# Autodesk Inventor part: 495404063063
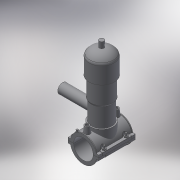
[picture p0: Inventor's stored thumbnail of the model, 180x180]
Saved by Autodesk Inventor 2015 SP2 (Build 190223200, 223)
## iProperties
Created: 2017-07
Part Number: 495404063063
Material: Generic
Description: PLASSON TAPPING VALVE 63-63
Document SubType Name: Modeling
Designer: KIM
Density: 1 g/cm^3
Appearance: Default
Author: KIM
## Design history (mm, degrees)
derived "495404-4954S4.ipt"
feature "Solid1::495404-4954S4.ipt"
feature "Solid2::495404-4954S4.ipt"
tag "TaggingFeature1"
body "Solid1"
body "Solid2"
other parameters: "d_" = 63, "B_" = 99, "H_" = 186, "L_" = 118, "d_t" = 6, "d_1" = 63, "H_1" = 51, "H_2" = 244, "d148" = 0.945, "d160" = 0.945, "d169" = 3, "d192" = 6.8, "d228" = 50.4, "d0" = 63, "d2" = 99, "d3" = 15.75, "d4" = 118, "d5" = 0, "d6" = 0.1, "d8" = 0, "d19" = 6, "d20" = 6, "d21" = 70.8, "d23" = 0, "d24" = 35.4, "d26" = 0, "d27" = 3, "d28" = 3, "d29" = 3, "d30" = 21, "d31" = 6, "d32" = 0, "d33" = 0, "d34" = 0.6, "d40" = 42.588, "d47" = 91.95, "d70" = 15, "d72" = 0, "d73" = 6, "d75" = 5, "d76" = 0, "d77" = 3.15, "d78" = 61.5, "d79" = 15, "d80" = 47.2, "d82" = 5 deg, "d84" = 4, "d85" = 14, "d86" = 0, "d87" = 3, "d88" = 0, "d89" = 1, "d90" = 1, "d91" = 94.4, "d92" = 0, "d93" = 0.5, "d94" = 33.15789, "d96" = 84.357, "d97" = 2.36, "d98" = 0, "d120" = 140 deg, "d121" = 24.228, "d122" = 20 deg, "d123" = 163.8, "d124" = 49.14, "d126" = 0, "d143" = 64.89, "d145" = 14.53846, "d149" = 0.945, "d150" = 15.99231, "d153" = 118, "d154" = 0, "d156" = 40.95, "d157" = 160 deg, "d159" = 3.78, "d161" = 0.945, "d162" = 70.8, "d163" = 0, "d164" = 31.5, "d167" = 6.3, "d168" = 39.95122, "d170" = 3, "d172" = 0, "d173" = 1, "d175" = 31.5, "d176" = 20 deg, "d177" = 4.41, "d178" = 18.9, "d180" = 0, "d183" = 7.56, "d184" = 3.528, "d185" = 38.35, "d186" = 38.35, "d187" = 40.95, "d188" = 5.67, "d189" = 4.41, "d190" = 0, "d191" = 61.425, "d193" = 6.8, "d194" = 2.95, "d195" = 90 deg, "d197" = 0, "d199" = 0, "d205" = 14.64, "d206" = 81.33333, "d207" = 244, "d208" = 224.48, "d209" = 207.4, "d210" = 200.08, "d211" = 146.4, "d212" = 85.4, "d213" = 65.88, "d214" = 73.2, "d216" = 19.52, "d217" = 70.76, "d218" = 80.52, "d220" = 63, "d222" = 0, "d223" = 81.9, "d224" = 186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
